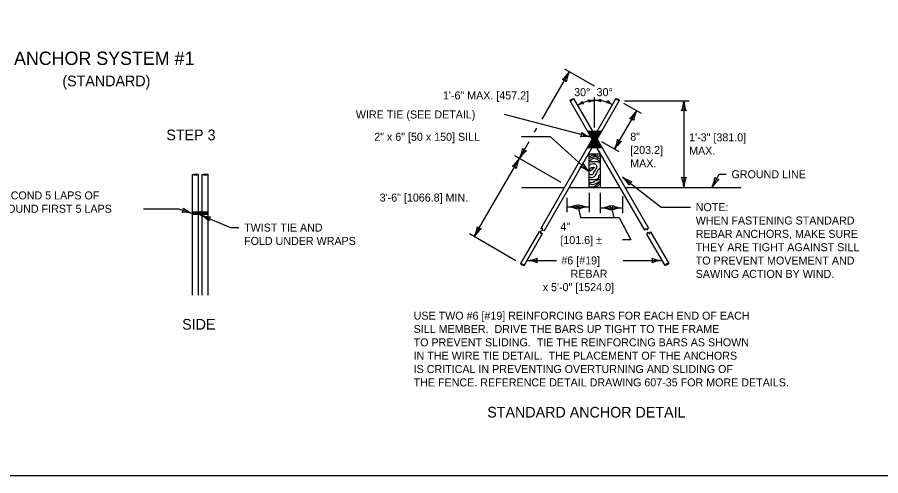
# Model space of a CAD drawing. Extents: x 49991.4 to 50021, y 49987.6 to 50011.4.
# Drawn here: x 50004.94 to 50011.41, y 49987.8 to 49991.23 of the extents above; entities that cross this region are included whole.
import ezdxf

# ---------------------------------------------------------------- set-up
doc = ezdxf.new("R2010")
doc.units = 0
for name, color, linetype in [('Level 1', 7, 'Continuous'), ('Level 2', 7, 'Continuous'), ('Level 3', 7, 'Continuous')]:
    doc.layers.add(name, color=color, linetype=linetype)

msp = doc.modelspace()

# ---------------------------------------------------------------- linework, layer by layer
at = {"layer": 'Level 1'}
for p, q in [((50009.2477, 49990.3199), (50009.081, 49990.6086)), ((50009.1081, 49990.6243), (50009.2658, 49990.3512)), ((50009.4234, 49990.6242), (50009.2658, 49990.3512)), ((50009.2838, 49990.3201), (50009.4504, 49990.6086)), ((50009.2477, 49990.3199), (50008.8615, 49989.6511)), ((50009.2133, 49990.3795), (50009.3181, 49990.3795)), ((50009.2157, 49990.3753), (50009.3157, 49990.3753)), ((50009.2181, 49990.3711), (50009.3133, 49990.3711)), ((50009.2205, 49990.367), (50009.3109, 49990.367)), ((50009.2229, 49990.3628), (50009.3085, 49990.3628)), ((50009.2254, 49990.3586), (50009.3061, 49990.3586)), ((50009.2277, 49990.3545), (50009.3037, 49990.3545)), ((50009.2301, 49990.3503), (50009.3013, 49990.3503)), ((50009.2326, 49990.3461), (50009.2989, 49990.3461)), ((50009.2349, 49990.342), (50009.2965, 49990.342)), ((50009.2374, 49990.3378), (50009.2941, 49990.3378)), ((50009.2398, 49990.3336), (50009.2917, 49990.3336)), ((50009.2422, 49990.3295), (50009.2893, 49990.3295)), ((50009.2446, 49990.3253), (50009.2869, 49990.3253)), ((50009.247, 49990.3211), (50009.2844, 49990.3211)), ((50009.2838, 49990.3201), (50009.6682, 49989.6542)), ((50008.8886, 49989.6354), (50009.2657, 49990.2887)), ((50009.2123, 49990.2586), (50009.3193, 49990.2586)), ((50009.2147, 49990.2628), (50009.3169, 49990.2628)), ((50009.2172, 49990.267), (50009.3145, 49990.267)), ((50009.2195, 49990.2711), (50009.3121, 49990.2711)), ((50009.2219, 49990.2753), (50009.3097, 49990.2753)), ((50009.2244, 49990.2795), (50009.3073, 49990.2795)), ((50009.2267, 49990.2836), (50009.3049, 49990.2836)), ((50009.2292, 49990.2878), (50009.3025, 49990.2878)), ((50009.2316, 49990.292), (50009.3, 49990.292)), ((50009.234, 49990.2961), (50009.2977, 49990.2961)), ((50009.2364, 49990.3003), (50009.2952, 49990.3003)), ((50009.2388, 49990.3045), (50009.2928, 49990.3045)), ((50009.2412, 49990.3086), (50009.2905, 49990.3086)), ((50009.2436, 49990.3128), (50009.288, 49990.3128)), ((50009.246, 49990.317), (50009.2856, 49990.317)), ((50009.6412, 49989.6385), (50009.2657, 49990.2887)), ((50009.2241, 49990.2091), (50009.3074, 49990.2091)), ((50009.2241, 49989.9591), (50009.2241, 49990.2091)), ((50009.3074, 49990.2091), (50009.3074, 49989.9591)), ((50006.2512, 49989.1505), (50006.2512, 49990.0557)), ((50006.2959, 49989.1505), (50006.2959, 49990.0557)), ((50006.324, 49989.1505), (50006.324, 49990.0557)), ((50006.3687, 49989.1505), (50006.3687, 49990.0557)), ((50006.2512, 49989.7757), (50006.3687, 49989.7757)), ((50006.2512, 49989.7742), (50006.3687, 49989.7742)), ((50006.2512, 49989.7715), (50006.3687, 49989.7715)), ((50006.2512, 49989.77), (50006.3687, 49989.77)), ((50006.2512, 49989.7673), (50006.3687, 49989.7673)), ((50006.2512, 49989.7658), (50006.3687, 49989.7658)), ((50006.2512, 49989.7632), (50006.3687, 49989.7632)), ((50006.2512, 49989.7617), (50006.3687, 49989.7617)), ((50006.2512, 49989.759), (50006.3687, 49989.759)), ((50006.2512, 49989.7575), (50006.3687, 49989.7575)), ((50008.8486, 49989.6287), (50008.7101, 49989.3888)), ((50008.7376, 49989.374), (50008.8757, 49989.613)), ((50008.8486, 49989.6287), (50008.8513, 49989.6271)), ((50008.8513, 49989.6271), (50008.8598, 49989.6325)), ((50008.8598, 49989.6325), (50008.8588, 49989.6125)), ((50008.8588, 49989.6125), (50008.8672, 49989.6179)), ((50008.8615, 49989.6511), (50008.863, 49989.6502)), ((50008.863, 49989.6502), (50008.8714, 49989.6556)), ((50008.8672, 49989.6179), (50008.8757, 49989.613)), ((50008.8714, 49989.6556), (50008.8704, 49989.6356)), ((50008.8704, 49989.6356), (50008.8789, 49989.641)), ((50008.8789, 49989.641), (50008.8886, 49989.6354)), ((50009.6412, 49989.6385), (50009.6455, 49989.641)), ((50009.6455, 49989.641), (50009.645, 49989.6511)), ((50009.645, 49989.6511), (50009.6619, 49989.6402)), ((50009.658, 49989.6093), (50009.6629, 49989.6122)), ((50009.794, 49989.374), (50009.658, 49989.6093)), ((50009.6614, 49989.6502), (50009.6682, 49989.6542)), ((50009.6619, 49989.6402), (50009.6614, 49989.6502)), ((50009.6629, 49989.6122), (50009.6625, 49989.6222)), ((50009.6625, 49989.6222), (50009.6793, 49989.6113)), ((50009.6788, 49989.6213), (50009.6851, 49989.625)), ((50009.6793, 49989.6113), (50009.6788, 49989.6213)), ((50009.6851, 49989.625), (50009.8213, 49989.3889))]:
    msp.add_line(p, q, dxfattribs=at)
for points in [[(49999.3835, 49998.9992), (50016.7501, 49998.9992), (50016.7501, 49987.7988), (49999.3835, 49987.7988)], [(50006.3047, 49989.7782), (50006.3139, 49989.7782), (50006.3139, 49989.7531), (50006.3047, 49989.7531)]]:
    msp.add_lwpolyline(points, close=True, dxfattribs=at)
for points in [[(50009.081, 49990.6086), (50009.0974, 49990.6146), (50009.1081, 49990.6243)], [(50009.081, 49990.6086), (50009.0963, 49990.6208), (50009.1081, 49990.6243)], [(50009.4234, 49990.6242), (50009.442, 49990.619), (50009.4504, 49990.6086)], [(50009.4234, 49990.6242), (50009.4369, 49990.6168), (50009.4504, 49990.6086)], [(50009.2241, 49990.1909), (50009.2303, 49990.1927), (50009.2397, 49990.195), (50009.2492, 49990.2021), (50009.2663, 49990.2021), (50009.2799, 49990.1962), (50009.294, 49990.1938), (50009.3074, 49990.2002)], [(50009.2241, 49990.1809), (50009.2368, 49990.1809), (50009.2492, 49990.185), (50009.2627, 49990.1921), (50009.2734, 49990.1915), (50009.3, 49990.1762), (50009.3074, 49990.1753)], [(50009.2241, 49990.1543), (50009.2356, 49990.1621), (50009.245, 49990.1709), (50009.2669, 49990.1768), (50009.284, 49990.1692), (50009.3074, 49990.1495)], [(50009.3074, 49990.1376), (50009.3052, 49990.1415), (50009.2669, 49990.1515), (50009.2368, 49990.1497), (50009.2241, 49990.1461)], [(50009.2241, 49990.1225), (50009.2332, 49990.1321), (50009.2527, 49990.138), (50009.2775, 49990.1286), (50009.2752, 49990.0974), (50009.2575, 49990.0715), (50009.248, 49990.0539), (50009.2368, 49990.0527), (50009.2241, 49990.0604)], [(50006.2512, 49990.0557), (50006.2878, 49990.0582), (50006.2959, 49990.0557)], [(50006.324, 49990.0557), (50006.3606, 49990.0582), (50006.3687, 49990.0557)], [(50009.2241, 49990.0362), (50009.2539, 49990.035), (50009.2698, 49990.0474), (50009.3017, 49990.1009), (50009.3074, 49990.1053)], [(50009.2409, 49990.1086), (50009.2303, 49990.0933), (50009.2332, 49990.0839), (50009.248, 49990.0921), (50009.2622, 49990.1097), (50009.2504, 49990.1086), (50009.2409, 49990.1086)], [(50006.2512, 49990.0557), (50006.2738, 49990.053), (50006.2959, 49990.0557)], [(50006.324, 49990.0557), (50006.3466, 49990.053), (50006.3687, 49990.0557)], [(50009.2241, 49990.0179), (50009.2362, 49990.0186), (50009.2592, 49990.0186), (50009.297, 49990.0339), (50009.2976, 49990.0456), (50009.3052, 49990.0527), (50009.3074, 49990.0535)], [(50009.2241, 49989.9999), (50009.2456, 49989.9951), (50009.2639, 49990.0045), (50009.2899, 49990.0151), (50009.3074, 49990.0234)], [(50009.2241, 49989.9879), (50009.2445, 49989.9815), (50009.3074, 49990.0083)], [(50009.2241, 49989.9663), (50009.2681, 49989.9674), (50009.2822, 49989.9804), (50009.3074, 49990.0007)], [(50009.2606, 49989.9591), (50009.2745, 49989.9627), (50009.2887, 49989.971), (50009.3074, 49989.9841)], [(50008.7101, 49989.3888), (50008.7219, 49989.3792), (50008.7376, 49989.374)], [(50008.7101, 49989.3888), (50008.7263, 49989.3836), (50008.7376, 49989.374)], [(50009.8213, 49989.3889), (50009.81, 49989.3777), (50009.794, 49989.374)], [(50009.8213, 49989.3889), (50009.8077, 49989.385), (50009.794, 49989.374)]]:
    msp.add_spline(points, degree=3, dxfattribs=at)
at = {"layer": 'Level 3'}
for p, q in [((50009.2633, 49990.7166), (50009.0416, 49990.8449)), ((50008.8719, 49990.471), (50009.0762, 49990.8248)), ((50009.2657, 49990.407), (50009.2657, 49990.6356)), ((50009.6157, 49990.5132), (50009.4851, 49990.5886)), ((50009.4904, 49990.6086), (50009.974, 49990.6086)), ((50009.934, 49990.6086), (50009.934, 49989.9591)), ((50009.4144, 49990.2446), (50009.5811, 49990.5332)), ((50009.2389, 49990.3351), (50008.5886, 49990.5051)), ((50008.8151, 49990.3726), (50008.8319, 49990.4017)), ((50008.9353, 49990.3379), (50008.7175, 49990.3379)), ((50009.2241, 49990.0746), (50008.9353, 49990.3379)), ((50008.7011, 49990.1753), (50008.7751, 49990.3033)), ((50009.4491, 49990.2246), (50009.3185, 49990.3)), ((50009.0138, 49989.9949), (50008.6666, 49990.1955)), ((50008.3631, 49989.5899), (50008.7011, 49990.1753)), ((50009.475, 49990.0365), (50009.7654, 49989.8108)), ((50010.1447, 49989.9591), (50010.2003, 49990.0572)), ((50010.2003, 49990.0572), (50010.2517, 49990.0572)), ((50008.7196, 49989.9591), (50009.0394, 49989.9591)), ((50009.0754, 49989.9591), (50009.456, 49989.9591)), ((50009.4922, 49989.9591), (50010.3622, 49989.9591)), ((50009.0574, 49989.8816), (50009.0574, 49989.7722)), ((50009.2241, 49989.9191), (50009.2241, 49989.7722)), ((50009.3074, 49989.9191), (50009.3074, 49989.7652)), ((50009.4741, 49989.8926), (50009.4741, 49989.7652)), ((50009.0574, 49989.8122), (50009.2241, 49989.8122)), ((50009.3074, 49989.8052), (50009.4741, 49989.8052)), ((50009.3908, 49989.8052), (50009.4082, 49989.7321)), ((50009.7654, 49989.8108), (50009.9833, 49989.8108)), ((50005.8845, 49989.7988), (50006.1459, 49989.7988)), ((50006.1459, 49989.7988), (50006.2512, 49989.764)), ((50006.3087, 49989.7531), (50006.5357, 49989.6577)), ((50006.5357, 49989.6577), (50006.5973, 49989.6577)), ((50008.6758, 49989.4095), (50008.3285, 49989.6099)), ((50008.7594, 49989.4115), (50008.9801, 49989.4115)), ((50009.4796, 49989.4115), (50009.7723, 49989.4115))]:
    msp.add_line(p, q, dxfattribs=at)
msp.add_lwpolyline([(50009.1408, 49989.8122), (50009.159, 49989.7321), (50009.4482, 49989.7321), (50009.5366, 49989.5648), (50009.4738, 49989.5648)], dxfattribs=at)
for centre, radius, start, end in [((50008.8884, 49990.9439), 0.2223, 307.45146, 327.63497), ((50009.2835, 49990.7184), 0.233, 152.82276, 172.07261), ((50009.0121, 49990.7138), 0.0548, 42.13427, 77.85663), ((50009.2768, 49990.3199), 0.2913, 92.18862, 118.80242), ((50009.074, 49990.6958), 0.1359, 297.37864, 316.62849), ((50009.1855, 49990.4551), 0.1297, 92.00734, 112.19085), ((50009.2045, 49990.6062), 0.032, 186.69015, 222.41251), ((50009.2563, 49990.7403), 0.1297, 253.97276, 274.15627), ((50009.1914, 49990.6025), 0.032, 348.65557, 24.37793), ((50009.2878, 49990.4769), 0.1359, 99.34406, 118.59391), ((50009.2805, 49990.387), 0.2245, 58.68792, 94.37181), ((50009.2632, 49990.7469), 0.1359, 271.0593, 290.30915), ((50009.2564, 49990.4816), 0.1297, 65.688, 85.87151), ((50009.3405, 49990.6087), 0.032, 160.37081, 196.09317), ((50009.3333, 49990.6176), 0.032, 310.82674, 346.5491), ((50009.3323, 49990.4593), 0.1359, 61.51523, 80.76508), ((50009.4691, 49990.6867), 0.1297, 216.14393, 236.32744), ((50009.7119, 49990.6178), 0.2223, 337.45601, 357.63952), ((50010.1667, 49990.6201), 0.233, 182.82731, 202.07716), ((50009.3933, 49990.6522), 0.2223, 307.44459, 327.6281), ((50009.7883, 49990.4267), 0.233, 152.81589, 172.06574), ((50009.934, 49990.4804), 0.0548, 72.13882, 107.86118), ((50009.5169, 49990.4221), 0.0548, 42.1274, 77.84976), ((50009.1149, 49990.3675), 0.0548, 327.4887, 3.21106), ((50009.1912, 49990.107), 0.233, 78.17719, 97.42704), ((50009.304, 49990.5477), 0.2223, 232.80589, 252.9894), ((50009.2072, 49990.3511), 0.233, 332.81589, 352.06574), ((50009.4785, 49990.3556), 0.0548, 222.1274, 257.84976), ((50009.6022, 49990.1256), 0.2223, 127.44459, 147.6281), ((50008.4939, 49990.2819), 0.233, 332.82276, 352.07261), ((50008.889, 49990.0564), 0.2223, 127.45146, 147.63497), ((50008.7653, 49990.2865), 0.0548, 222.13427, 257.85663), ((50008.5134, 49990.2945), 0.2223, 307.45461, 327.63811), ((50008.9085, 49990.0691), 0.233, 152.82591, 172.07576), ((50009.1294, 49990.161), 0.0548, 299.77052, 335.49288), ((50009.3806, 49990.2325), 0.2223, 205.08771, 225.27122), ((50008.6371, 49990.0644), 0.0548, 42.13741, 77.85978), ((50009.0758, 49989.8949), 0.233, 50.45901, 69.70886), ((50009.3315, 49989.8667), 0.2223, 29.60839, 49.7919), ((50009.6087, 49990.2273), 0.233, 234.97969, 254.22954), ((50009.5762, 49989.9578), 0.0548, 124.2912, 160.01356), ((50009.934, 49990.0873), 0.0548, 252.13882, 287.86118), ((50009.7013, 49989.9476), 0.233, 2.82731, 22.07716), ((50010.1561, 49989.9499), 0.2223, 157.45601, 177.63952), ((50009.9469, 49990.0607), 0.2223, 332.81728, 353.00079), ((50010.3415, 49989.8344), 0.233, 128.37964, 147.62949), ((50010.2079, 49990.0706), 0.0548, 222.59562, 258.31798), ((50006.1295, 49989.8042), 0.0548, 323.84177, 359.56413), ((50006.3296, 49989.972), 0.2223, 229.15896, 249.34247), ((50009.0459, 49990.0449), 0.233, 272.82731, 292.07716), ((50009.0482, 49989.5901), 0.2223, 67.45601, 87.63952), ((50009.1856, 49989.8122), 0.0548, 162.13882, 197.86118), ((50009.2333, 49990.0343), 0.2223, 247.45601, 267.63952), ((50009.0959, 49989.8122), 0.0548, 342.13882, 17.86118), ((50009.2356, 49989.5795), 0.233, 92.82731, 112.07716), ((50009.2959, 49990.0379), 0.233, 272.82731, 292.07716), ((50009.2982, 49989.5831), 0.2223, 67.45601, 87.63952), ((50009.4356, 49989.8052), 0.0548, 162.13882, 197.86118), ((50009.4833, 49990.0273), 0.2223, 247.45601, 267.63952), ((50009.3459, 49989.8052), 0.0548, 342.13882, 17.86118), ((50009.4856, 49989.5725), 0.233, 92.82731, 112.07716), ((50006.1891, 49989.5394), 0.233, 74.53026, 93.78011), ((50006.2145, 49989.5517), 0.2223, 44.74616, 64.92967), ((50006.388, 49989.9722), 0.233, 250.11746, 269.36731), ((50006.427, 49989.7036), 0.0548, 139.42897, 175.15133), ((50008.1558, 49989.6963), 0.233, 332.82591, 352.07576), ((50008.5509, 49989.4709), 0.2223, 127.45461, 147.63811), ((50008.4272, 49989.701), 0.0548, 222.13741, 257.85978), ((50008.7478, 49989.6442), 0.233, 272.82731, 292.07716), ((50008.7501, 49989.1894), 0.2223, 67.45601, 87.63952), ((50008.8875, 49989.4115), 0.0548, 162.13882, 197.86118), ((50009.7815, 49989.6336), 0.2223, 247.45601, 267.63952), ((50009.6441, 49989.4115), 0.0548, 342.13882, 17.86118), ((50009.7838, 49989.1788), 0.233, 92.82731, 112.07716)]:
    msp.add_arc(centre, radius, start, end, dxfattribs=at)

# ---------------------------------------------------------------- texts
at = {"layer": 'Level 2'}
for s, height, p in [('ANCHOR SYSTEM #1', 0.1, (50004.9125, 49990.8761)), ('(STANDARD)', 0.08, (50005.275, 49990.7161)), ('1\'-6" MAX. [457.2]', 0.06, (50008.1282, 49990.6179)), ('30°', 0.06, (50009.1118, 49990.6423)), ('30°', 0.06, (50009.2802, 49990.6425)), ('WIRE TIE (SEE DETAIL)', 0.06, (50007.4755, 49990.4751)), ('STEP 3', 0.08, (50006.0546, 49990.3122)), ('2" x 6" [50 x 150] SILL', 0.06, (50007.6131, 49990.3079)), ('8"', 0.06, (50009.5324, 49990.3089)), ('1\'-3" [381.0]', 0.06, (50009.974, 49990.3038)), ('[203.2]', 0.06, (50009.5324, 49990.2089)), ('MAX.', 0.06, (50009.974, 49990.2038)), ('MAX.', 0.06, (50009.5324, 49990.1089)), ('GROUND LINE', 0.06, (50010.2917, 49990.0272)), ('WRAP SECOND 5 LAPS OF', 0.06, (50004.5177, 49989.8688)), ('3\'-6" [1066.8] MIN.', 0.06, (50007.6537, 49989.8526)), ('WIRE AROUND FIRST 5 LAPS', 0.06, (50004.5177, 49989.7688)), ('NOTE: ', 0.06, (50010.0233, 49989.7808)), ('WHEN FASTENING STANDARD', 0.06, (50010.0233, 49989.6808)), ('TWIST TIE AND', 0.06, (50006.6373, 49989.6277)), ('4"', 0.06, (50009.0089, 49989.6348)), ('REBAR ANCHORS, MAKE SURE', 0.06, (50010.0233, 49989.5808)), ('FOLD UNDER WRAPS', 0.06, (50006.6373, 49989.5277)), ('[101.6] ±', 0.06, (50009.0089, 49989.5348)), ('THEY ARE TIGHT AGAINST SILL', 0.06, (50010.0233, 49989.4808)), ('#6 [#19]', 0.06, (50009.016, 49989.3815)), ('TO PREVENT MOVEMENT AND ', 0.06, (50010.0233, 49989.3808)), ('REBAR', 0.06, (50009.0851, 49989.2815)), ('SAWING ACTION BY WIND.', 0.06, (50010.0233, 49989.2808)), ('x 5\'-0" [1524.0]', 0.06, (50008.8762, 49989.1815)), ('USE TWO #6 [#19] REINFORCING BARS FOR EACH END OF EACH', 0.06, (50007.9086, 49988.968)), ('SIDE', 0.08, (50006.1732, 49988.8932)), ('SILL MEMBER.  DRIVE THE BARS UP TIGHT TO THE FRAME', 0.06, (50007.9086, 49988.868)), ('TO PREVENT SLIDING.  TIE THE REINFORCING BARS AS SHOWN', 0.06, (50007.9086, 49988.768)), ('IN THE WIRE TIE DETAIL.  THE PLACEMENT OF THE ANCHORS', 0.06, (50007.9086, 49988.668)), ('IS CRITICAL IN PREVENTING OVERTURNING AND SLIDING OF', 0.06, (50007.9086, 49988.568)), ('THE FENCE. REFERENCE DETAIL DRAWING 607-35 FOR MORE DETAILS.', 0.06, (50007.9086, 49988.468)), ('STANDARD ANCHOR DETAIL', 0.08, (50008.4605, 49988.2346))]:
    msp.add_text(s, height=height, dxfattribs=at).set_placement(p)

doc.saveas('drawing.dxf')
